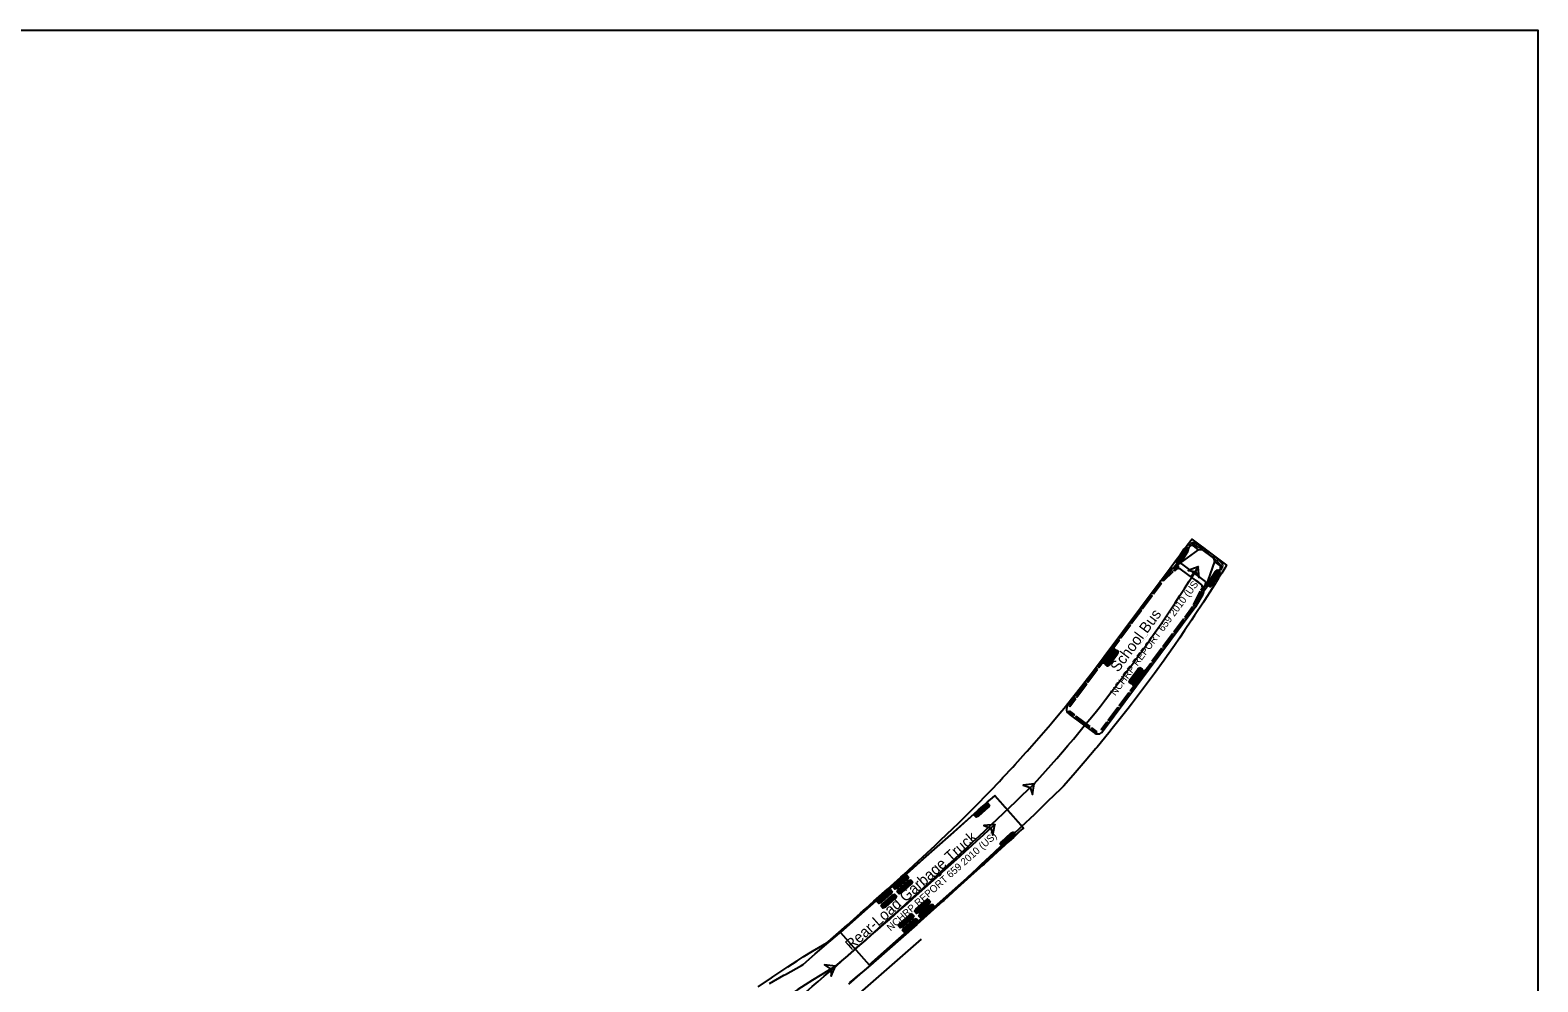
# Model space of a CAD drawing. Extents: x 973688 to 979179, y 703586 to 707602.
# Drawn here: x 977920.5 to 978198.5, y 704469.8 to 704645.4 of the extents above; entities that cross this region are included whole.
import ezdxf

# ---------------------------------------------------------------- set-up
doc = ezdxf.new("R2010")
doc.units = 0
for name, color, linetype in [('0-NPLT', 7, 'Continuous'), ('NB Right', 7, 'Continuous'), ('NO PLOT', 7, 'Continuous')]:
    doc.layers.add(name, color=color, linetype=linetype)

msp = doc.modelspace()

# ---------------------------------------------------------------- linework, layer by layer
at = {"layer": '0-NPLT'}
msp.add_line((978084.79, 704477.69), (978038.74, 704437.44), dxfattribs=at)
at = {"layer": 'NB Right'}
for p, q in [((978134.28, 704550.1), (978131.4, 704546.22)), ((978131.91, 704546.58), (978135.95, 704549.55)), ((978133.69, 704550.03), (978131.94, 704547.19)), ((978133.87, 704549.92), (978132.12, 704547.08)), ((978134.04, 704549.81), (978132.29, 704546.98)), ((978134.39, 704550.53), (978134.15, 704550.2)), ((978134.15, 704550.2), (978134.15, 704550.2)), ((978134.15, 704550.2), (978134.28, 704550.1)), ((978135.95, 704549.55), (978135.02, 704550.25)), ((978135.95, 704549.55), (978136.58, 704549.56)), ((978136.58, 704549.56), (978138.72, 704547.96)), ((978137.93, 704549.14), (978137.87, 704549.18)), ((978137.99, 704549.09), (978137.93, 704549.14)), ((978131.39, 704546.21), (978130.77, 704545.81)), ((978131.9, 704546.35), (978131.32, 704545.86)), ((978131.39, 704546.22), (978131.79, 704546.47)), ((978131.4, 704546.22), (978131.39, 704546.21)), ((978131.77, 704545.76), (978131.96, 704546.31)), ((978132.18, 704546.54), (978132.01, 704545.94)), ((978132.5, 704546.04), (978136.51, 704543.05)), ((978137.25, 704543.67), (978132.89, 704546.92)), ((978137.01, 704542.04), (978139.9, 704545.92)), ((978138.89, 704547.36), (978137.2, 704542.63)), ((978138.72, 704547.96), (978138.89, 704547.36)), ((978139.83, 704546.67), (978138.89, 704547.36)), ((978139.9, 704545.92), (978140.03, 704545.82)), ((978140.03, 704545.82), (978140.27, 704546.15)), ((978128.67, 704543.4), (978111.83, 704520.79)), ((978127.52, 704541.44), (978128.97, 704543.4)), ((978129.11, 704543.3), (978127.65, 704541.34)), ((978128.95, 704543.78), (978128.67, 704543.4)), ((978129.01, 704543.86), (978128.95, 704543.78)), ((978128.97, 704543.4), (978129.11, 704543.3)), ((978130.77, 704545.81), (978129.01, 704543.86)), ((978129.31, 704543.85), (978130.92, 704545.69)), ((978129.44, 704543.75), (978129.31, 704543.85)), ((978131.19, 704545.49), (978129.44, 704543.75)), ((978130.69, 704545), (978130.48, 704545.16)), ((978130.92, 704545.69), (978131.19, 704545.49)), ((978131.32, 704545.86), (978131.59, 704545.66)), ((978131.59, 704545.66), (978131.77, 704545.76)), ((978135.07, 704545.3), (978134.51, 704544.54)), ((978137.17, 704543.01), (978137.31, 704543.49)), ((978139.48, 704545.81), (978137.72, 704542.98)), ((978139.66, 704545.7), (978137.9, 704542.87)), ((978139.84, 704545.59), (978138.08, 704542.76)), ((978140.03, 704545.82), (978140.03, 704545.82)), ((978125.5, 704538.73), (978127.29, 704541.14)), ((978127.42, 704541.04), (978125.63, 704538.63)), ((978127.29, 704541.14), (978127.42, 704541.04)), ((978127.65, 704541.34), (978127.52, 704541.44)), ((978135.02, 704539.37), (978136.3, 704541.93)), ((978135.27, 704539.42), (978135.68, 704540.4)), ((978135.43, 704539.08), (978136.79, 704541.33)), ((978136.15, 704540.28), (978135.66, 704540.65)), ((978135.68, 704540.4), (978135.88, 704540.25)), ((978136.32, 704541.67), (978135.84, 704540.75)), ((978135.84, 704540.75), (978136.04, 704540.6)), ((978136.04, 704540.6), (978136.59, 704541.48)), ((978136.3, 704541.93), (978136.83, 704541.53)), ((978136.59, 704541.48), (978136.32, 704541.67)), ((978136.41, 704542.08), (978136.46, 704542.28)), ((978136.68, 704541.88), (978136.41, 704542.08)), ((978136.46, 704542.28), (978136.92, 704542.61)), ((978136.56, 704542.55), (978137.08, 704542.89)), ((978136.97, 704542.55), (978136.68, 704541.88)), ((978136.79, 704541.33), (978137, 704542.03)), ((978137.13, 704542.49), (978136.99, 704542.02)), ((978137, 704542.03), (978137.01, 704542.04)), ((978118.26, 704516.01), (978135.09, 704538.62)), ((978123.48, 704536.02), (978125.27, 704538.43)), ((978125.41, 704538.33), (978123.61, 704535.92)), ((978125.27, 704538.43), (978125.41, 704538.33)), ((978125.63, 704538.63), (978125.5, 704538.73)), ((978134.86, 704539.02), (978133.4, 704537.06)), ((978133.54, 704536.96), (978134.99, 704538.92)), ((978134.99, 704538.92), (978134.86, 704539.02)), ((978135.42, 704539.07), (978135.02, 704539.37)), ((978135.09, 704538.62), (978135.38, 704539)), ((978135.33, 704539.37), (978135.27, 704539.42)), ((978135.88, 704540.25), (978135.33, 704539.37)), ((978135.38, 704539), (978135.43, 704539.08)), ((978121.46, 704533.31), (978123.26, 704535.72)), ((978123.39, 704535.62), (978121.6, 704533.21)), ((978123.26, 704535.72), (978123.39, 704535.62)), ((978123.61, 704535.92), (978123.48, 704536.02)), ((978133.18, 704536.76), (978131.39, 704534.35)), ((978131.52, 704534.25), (978133.31, 704536.66)), ((978133.31, 704536.66), (978133.18, 704536.76)), ((978133.4, 704537.06), (978133.54, 704536.96)), ((978121.24, 704533.01), (978119.45, 704530.6)), ((978119.58, 704530.5), (978121.37, 704532.91)), ((978121.37, 704532.91), (978121.24, 704533.01)), ((978121.6, 704533.21), (978121.46, 704533.31)), ((978131.16, 704534.05), (978129.37, 704531.64)), ((978129.5, 704531.54), (978131.3, 704533.95)), ((978131.3, 704533.95), (978131.16, 704534.05)), ((978131.39, 704534.35), (978131.52, 704534.25)), ((978119.22, 704530.3), (978117.43, 704527.89)), ((978117.56, 704527.79), (978119.35, 704530.2)), ((978120.11, 704531.55), (978118.12, 704528.87)), ((978120.27, 704531.42), (978118.28, 704528.75)), ((978120.44, 704531.3), (978118.45, 704528.62)), ((978120.77, 704531.05), (978118.78, 704528.37)), ((978120.94, 704530.92), (978118.95, 704528.25)), ((978121.11, 704530.8), (978119.12, 704528.12)), ((978119.35, 704530.2), (978119.22, 704530.3)), ((978119.45, 704530.6), (978119.58, 704530.5)), ((978129.14, 704531.34), (978127.35, 704528.93)), ((978127.49, 704528.83), (978129.28, 704531.24)), ((978129.28, 704531.24), (978129.14, 704531.34)), ((978129.37, 704531.64), (978129.5, 704531.54)), ((978117.2, 704527.59), (978115.41, 704525.18)), ((978115.54, 704525.08), (978117.34, 704527.49)), ((978117.34, 704527.49), (978117.2, 704527.59)), ((978117.43, 704527.89), (978117.56, 704527.79)), ((978125.19, 704527.76), (978123.2, 704525.09)), ((978125.35, 704527.64), (978123.36, 704524.97)), ((978125.52, 704527.51), (978123.53, 704524.84)), ((978125.85, 704527.27), (978123.86, 704524.59)), ((978126.02, 704527.14), (978124.03, 704524.47)), ((978126.19, 704527.02), (978124.2, 704524.34)), ((978125.33, 704526.22), (978127.13, 704528.63)), ((978127.26, 704528.53), (978125.47, 704526.12)), ((978127.13, 704528.63), (978127.26, 704528.53)), ((978127.35, 704528.93), (978127.49, 704528.83)), ((978115.19, 704524.88), (978113.39, 704522.47)), ((978113.53, 704522.37), (978115.32, 704524.78)), ((978115.32, 704524.78), (978115.19, 704524.88)), ((978115.41, 704525.18), (978115.54, 704525.08)), ((978123.32, 704523.51), (978125.11, 704525.92)), ((978125.24, 704525.82), (978123.45, 704523.41)), ((978125.11, 704525.92), (978125.24, 704525.82)), ((978125.47, 704526.12), (978125.33, 704526.22)), ((978113.17, 704522.17), (978112.1, 704520.74)), ((978112.24, 704520.64), (978113.3, 704522.07)), ((978113.3, 704522.07), (978113.17, 704522.17)), ((978113.39, 704522.47), (978113.53, 704522.37)), ((978121.3, 704520.8), (978123.09, 704523.21)), ((978123.23, 704523.11), (978121.43, 704520.7)), ((978123.09, 704523.21), (978123.23, 704523.11)), ((978123.45, 704523.41), (978123.32, 704523.51)), ((978111.9, 704519.6), (978112.07, 704519.83)), ((978112.88, 704518.88), (978111.9, 704519.6)), ((978112.07, 704519.83), (978113.05, 704519.1)), ((978112.1, 704520.74), (978112.24, 704520.64)), ((978112.12, 704519.2), (978116.66, 704515.83)), ((978113.05, 704519.1), (978112.88, 704518.88)), ((978113.4, 704518.84), (978113.23, 704518.61)), ((978113.23, 704518.61), (978115.77, 704516.72)), ((978115.94, 704516.95), (978113.4, 704518.84)), ((978119.28, 704518.09), (978121.07, 704520.5)), ((978121.21, 704520.4), (978119.41, 704517.99)), ((978121.07, 704520.5), (978121.21, 704520.4)), ((978121.43, 704520.7), (978121.3, 704520.8)), ((978115.77, 704516.72), (978115.94, 704516.95)), ((978116.29, 704516.69), (978116.12, 704516.46)), ((978116.12, 704516.46), (978117.1, 704515.73)), ((978117.27, 704515.96), (978116.29, 704516.69)), ((978117.1, 704515.73), (978117.27, 704515.96)), ((978117.99, 704516.36), (978119.06, 704517.79)), ((978118.13, 704516.26), (978117.99, 704516.36)), ((978119.19, 704517.69), (978118.13, 704516.26)), ((978119.06, 704517.79), (978119.19, 704517.69)), ((978119.41, 704517.99), (978119.28, 704518.09)), ((978098.39, 704504.19), (978069.92, 704478.91)), ((978097.07, 704502.78), (978094.62, 704500.53)), ((978097.22, 704502.63), (978094.76, 704500.38)), ((978097.36, 704502.47), (978094.9, 704500.22)), ((978103.7, 704498.21), (978098.39, 704504.19)), ((978098.39, 704504.19), (978098.39, 704504.19)), ((978075.23, 704472.93), (978103.7, 704498.21)), ((978101.84, 704497.43), (978099.38, 704495.18)), ((978101.98, 704497.28), (978099.52, 704495.03)), ((978102.12, 704497.12), (978099.66, 704494.87)), ((978082.14, 704489.49), (978079.65, 704487.27)), ((978082.28, 704489.33), (978079.79, 704487.12)), ((978082.42, 704489.18), (978079.93, 704486.96)), ((978082.92, 704488.62), (978080.43, 704486.4)), ((978083.06, 704488.46), (978080.56, 704486.25)), ((978083.2, 704488.3), (978080.7, 704486.09)), ((978079.15, 704486.83), (978076.66, 704484.62)), ((978079.29, 704486.68), (978076.8, 704484.46)), ((978079.43, 704486.52), (978076.94, 704484.31)), ((978079.93, 704485.96), (978077.44, 704483.75)), ((978080.07, 704485.8), (978077.57, 704483.59)), ((978080.2, 704485.65), (978077.71, 704483.44)), ((978086.13, 704485), (978083.64, 704482.79)), ((978086.27, 704484.85), (978083.77, 704482.63)), ((978083.14, 704482.35), (978080.64, 704480.13)), ((978083.28, 704482.19), (978080.78, 704479.98)), ((978083.41, 704482.03), (978080.92, 704479.82)), ((978086.4, 704484.69), (978083.91, 704482.48)), ((978086.9, 704484.13), (978084.41, 704481.92)), ((978087.04, 704483.97), (978084.55, 704481.76)), ((978087.18, 704483.82), (978084.69, 704481.6)), ((978083.91, 704481.47), (978081.42, 704479.26)), ((978084.05, 704481.32), (978081.56, 704479.1)), ((978084.19, 704481.16), (978081.7, 704478.95)), ((978069.92, 704478.91), (978075.23, 704472.93))]:
    msp.add_line(p, q, dxfattribs=at)
for points in [[(978054.78, 704468.87), (978057.2, 704470.58), (978057.47, 704470.76), (978059.67, 704472.24), (978060.23, 704472.61), (978061.91, 704473.69), (978063.05, 704474.41), (978064.77, 704475.46), (978065.93, 704476.15), (978067.39, 704477), (978067.66, 704477.2), (978068.65, 704478.08), (978071.14, 704480.27), (978073.63, 704482.47), (978074.62, 704483.36), (978076.1, 704484.69), (978078.57, 704486.91), (978081.03, 704489.14), (978081.52, 704489.58), (978083.48, 704491.37), (978085.92, 704493.62), (978087.37, 704494.97), (978088.33, 704495.87), (978090.71, 704498.14), (978091.65, 704499.06), (978093.05, 704500.44), (978094.2, 704501.6), (978095.35, 704502.76), (978096.73, 704504.17), (978097.64, 704505.12), (978099.22, 704506.78), (978099.89, 704507.5), (978101.68, 704509.43), (978102.12, 704509.91), (978104.1, 704512.11), (978104.32, 704512.35), (978106.48, 704514.82), (978108.62, 704517.31), (978108.83, 704517.56), (978110.72, 704519.83), (978111.14, 704520.34), (978112.79, 704522.37), (978114.42, 704524.42), (978114.82, 704524.93), (978116.82, 704527.52), (978117.62, 704528.56), (978118.8, 704530.14), (978120.76, 704532.78), (978122.74, 704535.44), (978124.73, 704538.11), (978126.73, 704540.79), (978128.72, 704543.47), (978130.71, 704546.14), (978131.89, 704547.72), (978132.55, 704548.61), (978133.21, 704549.49), (978133.86, 704550.37), (978134.5, 704551.24), (978134.57, 704551.32), (978134.69, 704551.49), (978141.12, 704546.71), (978140.78, 704546.16), (978140.22, 704545.23), (978139.64, 704544.3), (978139.06, 704543.35), (978139, 704543.26), (978138.47, 704542.41), (978137.05, 704540.18), (978136.86, 704539.9), (978135.23, 704537.38), (978134.67, 704536.55), (978133.38, 704534.62), (978132.44, 704533.25), (978131.5, 704531.88), (978130.16, 704529.98), (978129.59, 704529.16), (978127.83, 704526.73), (978127.63, 704526.46), (978125.63, 704523.76), (978125.43, 704523.49), (978123.59, 704521.07), (978122.97, 704520.27), (978121.5, 704518.4), (978120.03, 704516.55), (978119.39, 704515.76), (978117.23, 704513.14), (978117.02, 704512.88), (978115.05, 704510.54), (978113.94, 704509.25), (978112.83, 704507.97), (978111.03, 704505.93), (978110.8, 704505.68), (978110.56, 704505.44), (978108.11, 704503.07), (978107.38, 704502.36), (978105.67, 704500.71), (978103.21, 704498.37), (978101.73, 704496.96), (978100.75, 704496.03), (978098.28, 704493.69), (978095.8, 704491.38), (978095.06, 704490.69), (978093.33, 704489.08), (978090.86, 704486.79), (978088.39, 704484.53), (978088.14, 704484.3), (978085.91, 704482.27), (978083.43, 704480.03), (978081.19, 704478.01), (978080.94, 704477.79), (978078.44, 704475.56), (978075.93, 704473.34), (978074.18, 704471.79), (978073.9, 704471.6), (978073.39, 704471.16), (978071.86, 704469.87), (978071.58, 704469.67)], [(978135.89, 704546.39), (978134.02, 704545.69), (978135.36, 704545.54), (978136.09, 704544.4), (978135.89, 704546.39)], [(978105.62, 704506.35), (978103.63, 704506.12), (978104.9, 704505.65), (978105.33, 704504.37), (978105.62, 704506.35)], [(978056.84, 704469.48), (978059.46, 704471.02), (978059.76, 704471.18), (978062.74, 704472.81), (978063.02, 704472.99), (978065.28, 704474.95), (978067.79, 704477.13), (978069.3, 704478.44), (978070.3, 704479.31), (978072.8, 704481.5), (978075.3, 704483.7), (978075.55, 704483.92), (978077.79, 704485.9), (978080.28, 704488.11), (978082.77, 704490.32), (978085.26, 704492.53), (978087.75, 704494.75), (978090.25, 704496.96), (978092.74, 704499.17), (978094.56, 704500.79), (978095.39, 704501.53), (978096.22, 704502.26), (978097.04, 704503), (978097.87, 704503.73), (978098.36, 704504.16), (978103.67, 704498.18), (978103.43, 704497.96), (978102.62, 704497.22), (978101.81, 704496.47), (978100.99, 704495.72), (978100.17, 704494.97), (978098.86, 704493.78), (978096.4, 704491.54), (978096.15, 704491.32), (978093.93, 704489.3), (978091.45, 704487.07), (978088.97, 704484.85), (978088.72, 704484.63), (978086.49, 704482.63), (978083.99, 704480.41), (978081.49, 704478.19), (978080.99, 704477.75), (978078.98, 704475.98), (978076.47, 704473.78), (978073.95, 704471.58), (978073.44, 704471.14), (978071.42, 704469.39)], [(978098.37, 704498.83), (978096.38, 704498.65), (978097.63, 704498.15), (978098.02, 704496.86), (978098.37, 704498.83)], [(978068.99, 704472.68), (978067, 704472.93), (978068.12, 704472.18), (978068.23, 704470.83), (978068.99, 704472.68)]]:
    msp.add_lwpolyline(points, dxfattribs=at)
for points in [[(978133.65, 704550.06), (978134.09, 704549.78), (978133.98, 704549.31), (978132.72, 704547.26), (978132.34, 704546.95), (978131.89, 704547.22), (978132.01, 704547.7), (978133.27, 704549.74)], [(978135.89, 704546.39), (978134.02, 704545.69), (978135.36, 704545.54), (978136.09, 704544.4)], [(978139.44, 704545.84), (978139.88, 704545.56), (978139.77, 704545.08), (978138.5, 704543.04), (978138.12, 704542.73), (978137.68, 704543), (978137.79, 704543.48), (978139.06, 704545.52)], [(978120.06, 704531.58), (978120.48, 704531.27), (978120.33, 704530.8), (978118.9, 704528.87), (978118.49, 704528.59), (978118.07, 704528.9), (978118.23, 704529.37), (978119.66, 704531.3)], [(978120.73, 704531.08), (978121.15, 704530.77), (978121, 704530.3), (978119.56, 704528.37), (978119.16, 704528.09), (978118.74, 704528.4), (978118.9, 704528.87), (978120.33, 704530.8)], [(978125.14, 704527.79), (978125.56, 704527.48), (978125.41, 704527.02), (978123.98, 704525.09), (978123.57, 704524.81), (978123.15, 704525.12), (978123.31, 704525.59), (978124.74, 704527.51)], [(978125.81, 704527.3), (978126.23, 704526.99), (978126.08, 704526.52), (978124.64, 704524.59), (978124.24, 704524.31), (978123.82, 704524.62), (978123.98, 704525.09), (978125.41, 704527.02)], [(978105.62, 704506.35), (978103.63, 704506.12), (978104.9, 704505.65), (978105.33, 704504.37)], [(978097.04, 704502.82), (978097.39, 704502.44), (978097.15, 704502), (978095.38, 704500.38), (978094.93, 704500.18), (978094.58, 704500.57), (978094.82, 704501), (978096.59, 704502.62)], [(978098.37, 704498.83), (978096.38, 704498.65), (978097.63, 704498.15), (978098.02, 704496.86)], [(978101.81, 704497.47), (978102.16, 704497.09), (978101.92, 704496.65), (978100.15, 704495.03), (978099.7, 704494.83), (978099.35, 704495.22), (978099.59, 704495.65), (978101.36, 704497.27)], [(978082.11, 704489.53), (978082.45, 704489.14), (978082.21, 704488.71), (978080.42, 704487.12), (978079.96, 704486.92), (978079.62, 704487.31), (978079.86, 704487.74), (978081.66, 704489.33)], [(978082.88, 704488.65), (978083.23, 704488.27), (978082.98, 704487.84), (978081.19, 704486.25), (978080.74, 704486.05), (978080.39, 704486.44), (978080.64, 704486.87), (978082.43, 704488.46)], [(978079.12, 704486.87), (978079.46, 704486.48), (978079.22, 704486.06), (978077.42, 704484.46), (978076.97, 704484.27), (978076.63, 704484.66), (978076.87, 704485.08), (978078.67, 704486.68)], [(978079.89, 704486), (978080.24, 704485.61), (978079.99, 704485.18), (978078.2, 704483.59), (978077.75, 704483.4), (978077.4, 704483.79), (978077.65, 704484.21), (978079.44, 704485.81)], [(978086.09, 704485.04), (978086.44, 704484.65), (978086.19, 704484.22), (978084.4, 704482.63), (978083.95, 704482.44), (978083.6, 704482.83), (978083.85, 704483.25), (978085.64, 704484.85)], [(978083.1, 704482.38), (978083.45, 704482), (978083.2, 704481.57), (978081.41, 704479.98), (978080.96, 704479.78), (978080.61, 704480.17), (978080.86, 704480.6), (978082.65, 704482.19)], [(978086.87, 704484.17), (978087.21, 704483.78), (978086.97, 704483.35), (978085.17, 704481.76), (978084.72, 704481.57), (978084.38, 704481.95), (978084.62, 704482.38), (978086.42, 704483.98)], [(978083.88, 704481.51), (978084.22, 704481.12), (978083.98, 704480.7), (978082.18, 704479.1), (978081.73, 704478.91), (978081.38, 704479.3), (978081.63, 704479.73), (978083.42, 704481.32)], [(978068.99, 704472.68), (978067, 704472.93), (978068.12, 704472.18), (978068.23, 704470.83)]]:
    msp.add_lwpolyline(points, close=True, dxfattribs=at)
for centre in [(978135.89, 704546.39), (978105.62, 704506.35), (978105.62, 704506.35), (978098.37, 704498.83), (978068.99, 704472.68), (978068.99, 704472.68)]:
    msp.add_circle(centre, 0.0417, dxfattribs=at)
for centre, radius, start, end in [((978134.73, 704549.8), 0.534, 56.8622, 146.6044), ((978134.97, 704550.08), 0.73, 64.2038, 141.9575), ((978134.94, 704550.08), 0.368, 72.8566, 136.7932), ((978128.25, 704536.13), 15.84, 54.0066, 64.5758), ((978128.02, 704535.69), 16.71, 58.185, 64.2038), ((978128.64, 704536.7), 15.52, 53.5149, 58.185), ((978128.31, 704536.21), 15.74, 53.3351, 54.0066), ((978128.31, 704536.21), 15.74, 52.6637, 53.3351), ((978128.24, 704536.13), 15.84, 42.0945, 52.6637), ((978128.68, 704536.68), 15.52, 48.4852, 53.1554), ((977906.54, 704688.27), 269.68, 317.5793, 328.2588), ((978131.93, 704546.31), 0.0412, 342.6882, 150.866), ((978132.31, 704545.74), 0.357, 57.0364, 145.7981), ((978132.38, 704546.48), 0.21, 122.6054, 163.9928), ((978132.79, 704546.79), 0.168, 55.2298, 124.6392), ((978127.89, 704535.78), 16.71, 42.4665, 48.4852), ((978139.49, 704546.26), 0.534, 320.0659, 49.8081), ((978139.69, 704546.54), 0.368, 329.8771, 33.8137), ((978139.68, 704546.57), 0.73, 324.7127, 42.4665), ((978137.15, 704543.54), 0.168, 342.0311, 51.4405), ((978136.28, 704542.78), 0.357, 320.8722, 49.6338), ((978136.94, 704542.58), 0.0412, 315.8043, 123.9821), ((978136.97, 704543.06), 0.21, 302.6775, 344.0649), ((978112.67, 704520.12), 1.07, 141.4556, 239.2483), ((978117.38, 704516.62), 1.07, 227.422, 325.2147), ((977436.85, 705197.28), 961.58, 311.10115, 314.06628), ((977106.34, 705582.58), 1469.24, 310.65761, 312.46985), ((978138.62, 704352.74), 138.69, 120.1381, 130.9185)]:
    msp.add_arc(centre, radius, start, end, dxfattribs=at)
for centre, start_param, end_param in [((978132.06, 704546.26), 4.279238, 4.71273), ((978136.85, 704542.69), 1.570455, 2.003947)]:
    msp.add_ellipse(centre, major_axis=(-0.228, -0.307), ratio=0.908168, start_param=start_param, end_param=end_param, dxfattribs=at)
at = {"layer": 'NO PLOT'}
msp.add_lwpolyline([(977518.51, 704645.43), (978198.51, 704645.43), (978198.51, 704205.43), (977518.51, 704205.43)], close=True, dxfattribs=at)

# ---------------------------------------------------------------- texts
at = {"layer": 'NB Right'}
for s, height, rotation, p in [('NCHRP REPORT 659 2010 (US)', 1.3333, 53.3351, (978120.6, 704522.5)), ('School Bus', 2, 53.3351, (978121.11, 704526.81)), ('(c) 2022 Transoft Solutions, Inc. All rights reserved.', 0.08, 53.3351, (978125.21, 704531.99)), ('Rear-Load Garbage Truck', 2, 41.6062, (978071.89, 704475.53)), ('NCHRP REPORT 659 2010 (US)', 1.3333, 41.6062, (978079.17, 704479.09)), ('(c) 2022 Transoft Solutions, Inc. All rights reserved.', 0.08, 41.6062, (978085.61, 704487.44))]:
    msp.add_text(s, height=height, rotation=rotation, dxfattribs=at).set_placement(p)

doc.saveas('drawing.dxf')
